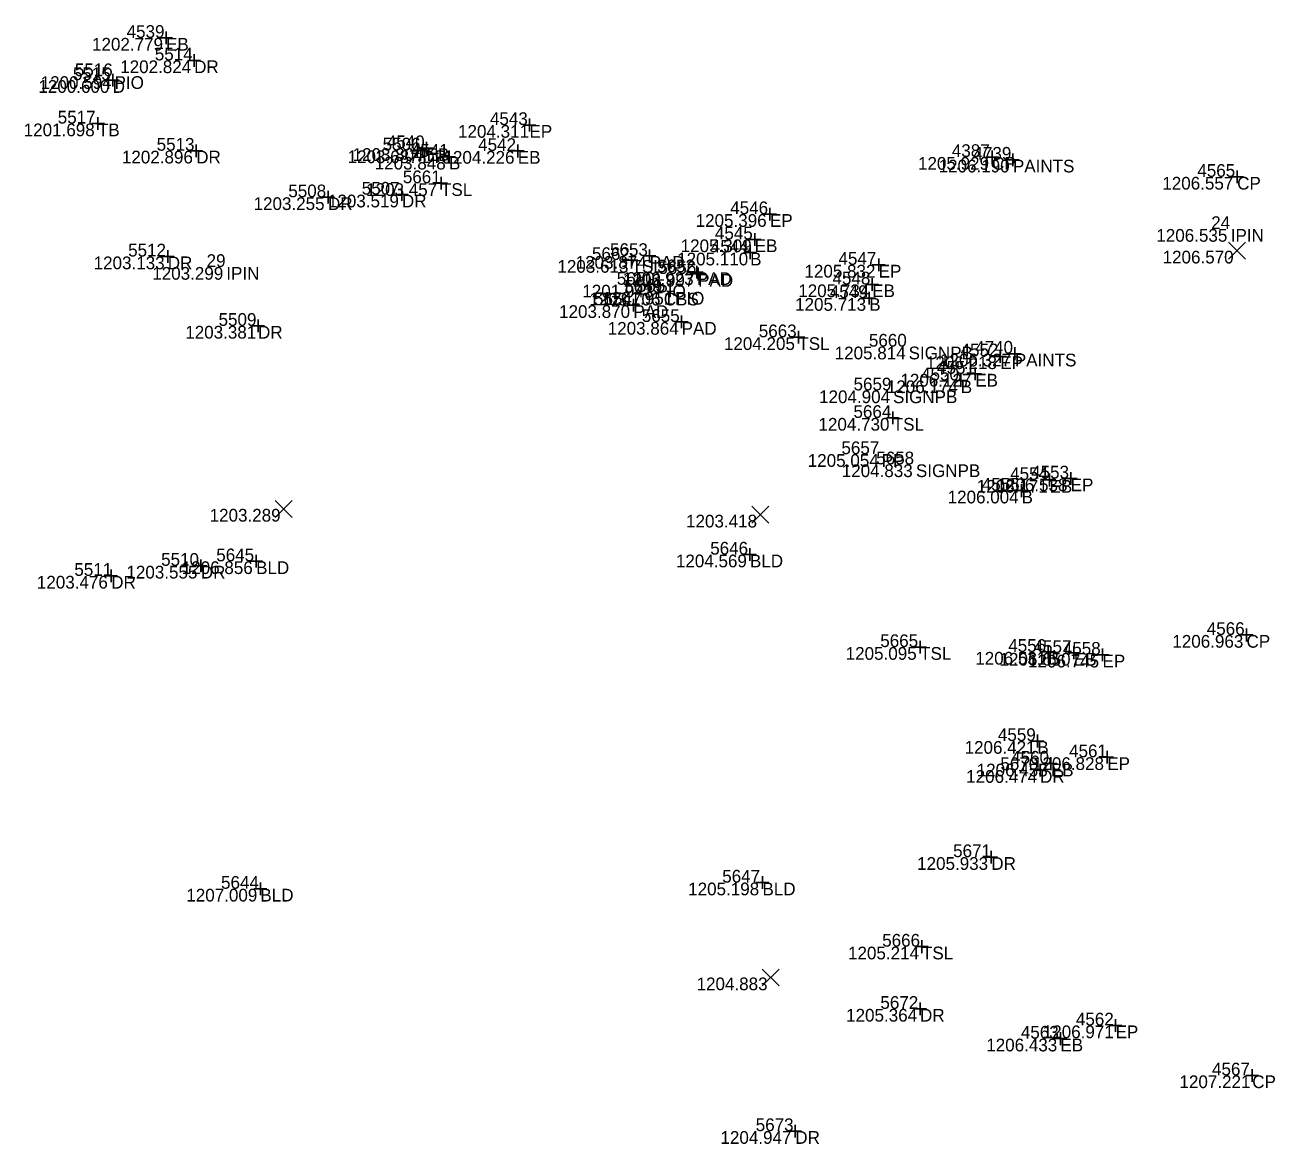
# Model space of a CAD drawing. Extents: x 2044997 to 2050342, y 455233 to 458054.
# Drawn here: x 2047537.7 to 2047635.9, y 456921.8 to 457009.8 of the extents above; entities that cross this region are included whole.
import ezdxf

# ---------------------------------------------------------------- set-up
doc = ezdxf.new("R2010")
doc.units = 0
for name, color, linetype in [('SV_X_Random_Point', 7, 'Continuous'), ('SV_X_Shot_Marker', 7, 'Continuous'), ('SV_X_Text_Comment', 7, 'Continuous'), ('SV_X_Text_Elevation', 7, 'Continuous'), ('SV_X_Text_Name', 7, 'Continuous')]:
    doc.layers.add(name, color=color, linetype=linetype)

msp = doc.modelspace()

# ---------------------------------------------------------------- linework, layer by layer
at = {"layer": 'SV_X_Random_Point'}
for p, q in [((2047632.207, 456991.355), (2047633.54, 456992.69)), ((2047632.207, 456992.69), (2047633.54, 456991.355)), ((2047557.318, 456971.065), (2047558.651, 456972.4)), ((2047557.318, 456972.4), (2047558.651, 456971.065)), ((2047594.766, 456970.602), (2047596.099, 456971.937)), ((2047594.766, 456971.937), (2047596.099, 456970.602)), ((2047595.582, 456934.228), (2047596.915, 456935.563)), ((2047595.582, 456935.563), (2047596.915, 456934.228))]:
    msp.add_line(p, q, dxfattribs=at)
at = {"layer": 'SV_X_Shot_Marker'}
for p, q in [((2047548.245, 457008.755), (2047549.245, 457008.755)), ((2047548.745, 457009.255), (2047548.745, 457008.255)), ((2047548.745, 457008.755), (2047548.745, 457008.755)), ((2047550.948, 457007.486), (2047550.948, 457006.486)), ((2047550.448, 457006.986), (2047551.448, 457006.986)), ((2047550.948, 457006.986), (2047550.948, 457006.986)), ((2047544.553, 457005.935), (2047544.553, 457004.935)), ((2047544.053, 457005.435), (2047545.053, 457005.435)), ((2047544.553, 457005.435), (2047544.553, 457005.435)), ((2047543.396, 457002.523), (2047543.396, 457001.523)), ((2047542.896, 457002.023), (2047543.896, 457002.023)), ((2047543.396, 457002.023), (2047543.396, 457002.023)), ((2047576.796, 457001.906), (2047577.796, 457001.906)), ((2047577.296, 457002.406), (2047577.296, 457001.406)), ((2047577.296, 457001.906), (2047577.296, 457001.906)), ((2047569.207, 457000.585), (2047569.207, 456999.585)), ((2047550.613, 456999.887), (2047551.613, 456999.887)), ((2047551.113, 457000.387), (2047551.113, 456999.387)), ((2047551.113, 456999.887), (2047551.113, 456999.887)), ((2047568.381, 456999.909), (2047569.381, 456999.909)), ((2047568.707, 457000.085), (2047569.707, 457000.085)), ((2047568.881, 457000.409), (2047568.881, 456999.409)), ((2047568.881, 456999.909), (2047568.881, 456999.909)), ((2047569.207, 457000.085), (2047569.207, 457000.085)), ((2047570.973, 456999.91), (2047570.973, 456998.91)), ((2047575.879, 456999.866), (2047576.879, 456999.866)), ((2047576.379, 457000.366), (2047576.379, 456999.366)), ((2047576.379, 456999.866), (2047576.379, 456999.866)), ((2047613.638, 456999.892), (2047613.638, 456998.892)), ((2047615.277, 456999.68), (2047615.277, 456998.68)), ((2047570.473, 456999.41), (2047571.473, 456999.41)), ((2047570.973, 456999.41), (2047570.973, 456999.41)), ((2047613.138, 456999.392), (2047614.138, 456999.392)), ((2047613.638, 456999.392), (2047613.638, 456999.392)), ((2047614.777, 456999.18), (2047615.777, 456999.18)), ((2047615.277, 456999.18), (2047615.277, 456999.18)), ((2047570.346, 456997.83), (2047570.346, 456996.83)), ((2047632.393, 456997.831), (2047633.393, 456997.831)), ((2047632.893, 456998.331), (2047632.893, 456997.331)), ((2047632.893, 456997.831), (2047632.893, 456997.831)), ((2047561.467, 456996.725), (2047561.467, 456995.725)), ((2047567.277, 456996.934), (2047567.277, 456995.934)), ((2047569.846, 456997.33), (2047570.846, 456997.33)), ((2047570.346, 456997.33), (2047570.346, 456997.33)), ((2047560.967, 456996.225), (2047561.967, 456996.225)), ((2047561.467, 456996.225), (2047561.467, 456996.225)), ((2047566.777, 456996.434), (2047567.777, 456996.434)), ((2047567.277, 456996.434), (2047567.277, 456996.434)), ((2047595.69, 456994.902), (2047596.69, 456994.902)), ((2047596.19, 456995.402), (2047596.19, 456994.402)), ((2047596.19, 456994.902), (2047596.19, 456994.902)), ((2047594.493, 456992.914), (2047595.493, 456992.914)), ((2047594.993, 456993.414), (2047594.993, 456992.414)), ((2047594.993, 456992.914), (2047594.993, 456992.914)), ((2047548.879, 456992.071), (2047548.879, 456991.071)), ((2047585.318, 456991.795), (2047585.318, 456990.795)), ((2047586.73, 456992.112), (2047586.73, 456991.112)), ((2047594.132, 456991.873), (2047595.132, 456991.873)), ((2047594.632, 456992.373), (2047594.632, 456991.373)), ((2047594.632, 456991.873), (2047594.632, 456991.873)), ((2047548.379, 456991.571), (2047549.379, 456991.571)), ((2047548.879, 456991.571), (2047548.879, 456991.571)), ((2047584.818, 456991.295), (2047585.818, 456991.295)), ((2047585.318, 456991.295), (2047585.318, 456991.295)), ((2047586.23, 456991.612), (2047587.23, 456991.612)), ((2047586.73, 456991.612), (2047586.73, 456991.612)), ((2047590.439, 456990.83), (2047590.439, 456989.83)), ((2047604.231, 456990.916), (2047605.231, 456990.916)), ((2047604.731, 456991.416), (2047604.731, 456990.416)), ((2047604.731, 456990.916), (2047604.731, 456990.916)), ((2047589.939, 456990.33), (2047590.939, 456990.33)), ((2047590.049, 456990.197), (2047591.049, 456990.197)), ((2047590.439, 456990.33), (2047590.439, 456990.33)), ((2047590.549, 456990.697), (2047590.549, 456989.697)), ((2047590.549, 456990.197), (2047590.549, 456990.197)), ((2047604.22, 456989.875), (2047604.22, 456988.875)), ((2047603.72, 456989.375), (2047604.72, 456989.375)), ((2047603.99, 456988.804), (2047603.99, 456987.804)), ((2047604.22, 456989.375), (2047604.22, 456989.375)), ((2047585.459, 456988.242), (2047585.459, 456987.242)), ((2047603.49, 456988.304), (2047604.49, 456988.304)), ((2047603.99, 456988.304), (2047603.99, 456988.304)), ((2047584.959, 456987.742), (2047585.959, 456987.742)), ((2047585.459, 456987.742), (2047585.459, 456987.742)), ((2047589.25, 456986.925), (2047589.25, 456985.925)), ((2047555.469, 456986.118), (2047556.469, 456986.118)), ((2047555.969, 456986.618), (2047555.969, 456985.618)), ((2047555.969, 456986.118), (2047555.969, 456986.118)), ((2047588.75, 456986.425), (2047589.75, 456986.425)), ((2047589.25, 456986.425), (2047589.25, 456986.425)), ((2047597.919, 456985.221), (2047598.919, 456985.221)), ((2047598.419, 456985.721), (2047598.419, 456984.721)), ((2047598.419, 456985.221), (2047598.419, 456985.221)), ((2047614.279, 456984.222), (2047614.279, 456983.222)), ((2047614.931, 456983.932), (2047615.931, 456983.932)), ((2047615.431, 456984.432), (2047615.431, 456983.432)), ((2047615.431, 456983.932), (2047615.431, 456983.932)), ((2047613.779, 456983.722), (2047614.779, 456983.722)), ((2047614.279, 456983.722), (2047614.279, 456983.722)), ((2047611.179, 456982.33), (2047611.179, 456981.33)), ((2047611.816, 456982.348), (2047612.816, 456982.348)), ((2047612.316, 456982.848), (2047612.316, 456981.848)), ((2047612.316, 456982.348), (2047612.316, 456982.348)), ((2047610.679, 456981.83), (2047611.679, 456981.83)), ((2047611.179, 456981.83), (2047611.179, 456981.83)), ((2047605.838, 456979.381), (2047605.838, 456978.381)), ((2047605.338, 456978.881), (2047606.338, 456978.881)), ((2047605.838, 456978.881), (2047605.838, 456978.881)), ((2047618.151, 456974.504), (2047618.151, 456973.504)), ((2047619.317, 456974.119), (2047620.317, 456974.119)), ((2047619.817, 456974.619), (2047619.817, 456973.619)), ((2047619.817, 456974.119), (2047619.817, 456974.119)), ((2047615.456, 456973.164), (2047616.456, 456973.164)), ((2047615.956, 456973.664), (2047615.956, 456972.664)), ((2047615.956, 456973.164), (2047615.956, 456973.164)), ((2047617.651, 456974.004), (2047618.651, 456974.004)), ((2047618.151, 456974.004), (2047618.151, 456974.004)), ((2047594.617, 456968.638), (2047594.617, 456967.638)), ((2047550.977, 456967.258), (2047551.977, 456967.258)), ((2047551.477, 456967.758), (2047551.477, 456966.758)), ((2047551.477, 456967.258), (2047551.477, 456967.258)), ((2047555.318, 456967.611), (2047556.318, 456967.611)), ((2047555.818, 456968.111), (2047555.818, 456967.111)), ((2047555.818, 456967.611), (2047555.818, 456967.611)), ((2047594.117, 456968.138), (2047595.117, 456968.138)), ((2047594.617, 456968.138), (2047594.617, 456968.138)), ((2047543.934, 456966.468), (2047544.934, 456966.468)), ((2047544.434, 456966.968), (2047544.434, 456965.968)), ((2047544.434, 456966.468), (2047544.434, 456966.468)), ((2047633.629, 456962.32), (2047633.629, 456961.32)), ((2047607.986, 456961.369), (2047607.986, 456960.369)), ((2047633.129, 456961.82), (2047634.129, 456961.82)), ((2047633.629, 456961.82), (2047633.629, 456961.82)), ((2047607.486, 456960.869), (2047608.486, 456960.869)), ((2047607.986, 456960.869), (2047607.986, 456960.869)), ((2047617.535, 456960.491), (2047618.535, 456960.491)), ((2047618.035, 456960.991), (2047618.035, 456959.991)), ((2047618.035, 456960.491), (2047618.035, 456960.491)), ((2047619.563, 456960.41), (2047620.563, 456960.41)), ((2047620.063, 456960.91), (2047620.063, 456959.91)), ((2047620.063, 456960.41), (2047620.063, 456960.41)), ((2047622.315, 456960.767), (2047622.315, 456959.767)), ((2047621.815, 456960.267), (2047622.815, 456960.267)), ((2047622.315, 456960.267), (2047622.315, 456960.267)), ((2047616.697, 456953.484), (2047617.697, 456953.484)), ((2047617.197, 456953.984), (2047617.197, 456952.984)), ((2047617.197, 456953.484), (2047617.197, 456953.484)), ((2047622.687, 456952.707), (2047622.687, 456951.707)), ((2047617.412, 456951.698), (2047617.412, 456950.698)), ((2047617.756, 456951.705), (2047618.756, 456951.705)), ((2047618.256, 456952.205), (2047618.256, 456951.205)), ((2047618.256, 456951.705), (2047618.256, 456951.705)), ((2047622.187, 456952.207), (2047623.187, 456952.207)), ((2047622.687, 456952.207), (2047622.687, 456952.207)), ((2047616.912, 456951.198), (2047617.912, 456951.198)), ((2047617.412, 456951.198), (2047617.412, 456951.198)), ((2047613.577, 456944.856), (2047613.577, 456943.856)), ((2047613.077, 456944.356), (2047614.077, 456944.356)), ((2047613.577, 456944.356), (2047613.577, 456944.356)), ((2047595.599, 456942.854), (2047595.599, 456941.854)), ((2047555.654, 456941.869), (2047556.654, 456941.869)), ((2047556.154, 456942.369), (2047556.154, 456941.369)), ((2047556.154, 456941.869), (2047556.154, 456941.869)), ((2047595.099, 456942.354), (2047596.099, 456942.354)), ((2047595.599, 456942.354), (2047595.599, 456942.354)), ((2047608.129, 456937.82), (2047608.129, 456936.82)), ((2047607.629, 456937.32), (2047608.629, 456937.32)), ((2047608.129, 456937.32), (2047608.129, 456937.32)), ((2047607.979, 456932.93), (2047607.979, 456931.93)), ((2047607.479, 456932.43), (2047608.479, 456932.43)), ((2047607.979, 456932.43), (2047607.979, 456932.43)), ((2047622.84, 456931.125), (2047623.84, 456931.125)), ((2047623.34, 456931.625), (2047623.34, 456930.625)), ((2047623.34, 456931.125), (2047623.34, 456931.125)), ((2047618.508, 456930.088), (2047619.508, 456930.088)), ((2047619.008, 456930.588), (2047619.008, 456929.588)), ((2047619.008, 456930.088), (2047619.008, 456930.088)), ((2047633.58, 456927.2), (2047634.58, 456927.2)), ((2047634.08, 456927.7), (2047634.08, 456926.7)), ((2047634.08, 456927.2), (2047634.08, 456927.2)), ((2047598.179, 456923.32), (2047598.179, 456922.32)), ((2047597.679, 456922.82), (2047598.679, 456922.82)), ((2047598.179, 456922.82), (2047598.179, 456922.82))]:
    msp.add_line(p, q, dxfattribs=at)

# ---------------------------------------------------------------- texts
at = {"layer": 'SV_X_Text_Comment'}
for s, p in [('EB', (2047548.745, 457007.755)), ('DR', (2047550.948, 457005.986)), ('PIO', (2047544.698, 457004.743)), ('D', (2047544.553, 457004.435)), ('TB', (2047543.396, 457001.023)), ('EP', (2047577.296, 457000.906)), ('DR', (2047551.113, 456998.887)), ('DR', (2047568.881, 456998.909)), ('EB', (2047569.207, 456999.085)), ('EB', (2047576.379, 456998.866)), ('B', (2047570.973, 456998.41)), ('CP', (2047613.638, 456998.392)), ('PAINTS', (2047615.277, 456998.18)), ('CP', (2047632.893, 456996.831)), ('TSL', (2047570.346, 456996.33)), ('DR', (2047561.467, 456995.225)), ('DR', (2047567.277, 456995.434)), ('EP', (2047596.19, 456993.902)), ('IPIN', (2047632.392, 456992.732)), ('EB', (2047594.993, 456991.914)), ('B', (2047594.632, 456990.873)), ('DR', (2047548.879, 456990.571)), ('IPIN', (2047553.477, 456989.746)), ('TSL', (2047585.318, 456990.295)), ('PAD', (2047586.73, 456990.612)), ('EP', (2047604.731, 456989.916)), ('PAD', (2047590.439, 456989.33)), ('PAD', (2047590.549, 456989.197)), ('PIO', (2047587.273, 456988.349)), ('PIO', (2047588.731, 456987.787)), ('EB', (2047604.22, 456988.375)), ('CBS', (2047587.843, 456987.726)), ('B', (2047603.99, 456987.304)), ('PAD', (2047585.459, 456986.742)), ('DR', (2047555.969, 456985.118)), ('PAD', (2047589.25, 456985.425)), ('TSL', (2047598.419, 456984.221)), ('SIGNPB', (2047607.081, 456983.486)), ('PAINTS', (2047615.431, 456982.932)), ('EP', (2047614.279, 456982.722)), ('EB', (2047612.316, 456981.348)), ('SIGNPB', (2047605.856, 456980.044)), ('B', (2047611.179, 456980.83)), ('TSL', (2047605.838, 456977.881)), ('PP', (2047604.965, 456975.036)), ('SIGNPB', (2047607.656, 456974.232)), ('EP', (2047619.817, 456973.119)), ('B', (2047615.956, 456972.164)), ('EB', (2047618.151, 456973.004)), ('DR', (2047551.477, 456966.258)), ('BLD', (2047555.818, 456966.611)), ('BLD', (2047594.617, 456967.138)), ('DR', (2047544.434, 456965.468)), ('CP', (2047633.629, 456960.82)), ('TSL', (2047607.986, 456959.869)), ('B', (2047618.035, 456959.491)), ('EB', (2047620.063, 456959.41)), ('EP', (2047622.315, 456959.267)), ('B', (2047617.197, 456952.484)), ('EB', (2047618.256, 456950.705)), ('EP', (2047622.687, 456951.207)), ('DR', (2047617.412, 456950.198)), ('DR', (2047613.577, 456943.356)), ('BLD', (2047556.154, 456940.869)), ('BLD', (2047595.599, 456941.354)), ('TSL', (2047608.129, 456936.32)), ('DR', (2047607.979, 456931.43)), ('EP', (2047623.34, 456930.125)), ('EB', (2047619.008, 456929.088)), ('CP', (2047634.08, 456926.2)), ('DR', (2047598.179, 456921.82))]:
    msp.add_text(s, height=1, dxfattribs=at).set_placement(p)
at = {"layer": 'SV_X_Text_Elevation'}
for s, p in [('1202.779', (2047542.927, 457007.755)), ('1202.824', (2047545.141, 457005.986)), ('1200.594', (2047538.89, 457004.743)), ('1200.600', (2047538.715, 457004.435)), ('1201.698', (2047537.56, 457001.023)), ('1204.311', (2047571.683, 457000.906)), ('1202.896', (2047545.273, 456998.887)), ('1203.687', (2047563.002, 456998.909)), ('1203.804', (2047563.4, 456999.085)), ('1204.226', (2047570.539, 456998.866)), ('1203.848', (2047565.137, 456998.41)), ('1205.929', (2047607.821, 456998.392)), ('1206.190', (2047609.439, 456998.18)), ('1206.557', (2047627.014, 456996.831)), ('1203.457', (2047564.466, 456996.33)), ('1203.255', (2047555.619, 456995.225)), ('1203.519', (2047561.459, 456995.434)), ('1205.396', (2047590.35, 456993.902)), ('1206.535', (2047626.545, 456992.732)), ('1205.309', (2047589.175, 456991.914)), ('1205.110', (2047588.898, 456990.873)), ('1206.570', (2047627.036, 456991.023)), ('1203.133', (2047543.053, 456990.571)), ('1203.299', (2047547.659, 456989.746)), ('1203.613', (2047579.492, 456990.295)), ('1203.874', (2047580.922, 456990.612)), ('1205.832', (2047598.898, 456989.916)), ('1203.923', (2047584.613, 456989.33)), ('1203.997', (2047584.669, 456989.197)), ('1201.943', (2047581.447, 456988.349)), ('1201.951', (2047583.013, 456987.787)), ('1205.734', (2047598.412, 456988.375)), ('1203.706', (2047582.002, 456987.726)), ('1205.713', (2047598.164, 456987.304)), ('1203.870', (2047579.622, 456986.742)), ('1203.381', (2047550.252, 456985.118)), ('1203.864', (2047583.442, 456985.425)), ('1204.205', (2047592.571, 456984.221)), ('1205.814', (2047601.273, 456983.486)), ('1206.327', (2047609.551, 456982.932)), ('1206.218', (2047608.443, 456982.722)), ('1206.127', (2047606.437, 456981.348)), ('1204.904', (2047600.048, 456980.044)), ('1206.174', (2047605.371, 456980.83)), ('1204.730', (2047600, 456977.881)), ('1205.054', (2047599.157, 456975.036)), ('1204.833', (2047601.829, 456974.232)), ('1206.538', (2047613.981, 456973.119)), ('1206.004', (2047610.148, 456972.164)), ('1206.171', (2047612.434, 456973.004)), ('1203.289', (2047552.166, 456970.733)), ('1203.418', (2047589.596, 456970.269)), ('1204.569', (2047588.799, 456967.138)), ('1203.555', (2047545.629, 456966.258)), ('1206.856', (2047549.977, 456966.611)), ('1203.476', (2047538.593, 456965.468)), ('1206.963', (2047627.802, 456960.82)), ('1205.095', (2047602.138, 456959.869)), ('1206.531', (2047612.318, 456959.491)), ('1206.650', (2047614.225, 456959.41)), ('1206.745', (2047616.468, 456959.267)), ('1206.421', (2047611.48, 456952.484)), ('1206.453', (2047612.43, 456950.705)), ('1206.828', (2047616.851, 456951.207)), ('1206.474', (2047611.604, 456950.198)), ('1205.933', (2047607.751, 456943.356)), ('1207.009', (2047550.336, 456940.869)), ('1205.198', (2047589.763, 456941.354)), ('1205.214', (2047602.321, 456936.32)), ('1204.883', (2047590.422, 456933.895)), ('1205.364', (2047602.171, 456931.43)), ('1206.971', (2047617.623, 456930.125)), ('1206.433', (2047613.182, 456929.088)), ('1207.221', (2047628.362, 456926.2)), ('1204.947', (2047592.299, 456921.82))]:
    msp.add_text(s, height=1, dxfattribs=at).set_placement(p)
at = {"layer": 'SV_X_Text_Name'}
for s, p in [('4539', (2047545.645, 457008.755)), ('5514', (2047547.859, 457006.986)), ('5516', (2047541.575, 457005.743)), ('5515', (2047541.423, 457005.435)), ('5517', (2047540.234, 457002.023)), ('4543', (2047574.188, 457001.906)), ('5513', (2047548.005, 456999.887)), ('5506', (2047565.759, 456999.909)), ('4540', (2047566.088, 457000.085)), ('4542', (2047573.264, 456999.866)), ('4541', (2047567.973, 456999.41)), ('4387', (2047610.477, 456999.392)), ('4739', (2047612.177, 456999.18)), ('4565', (2047629.764, 456997.831)), ('5661', (2047567.346, 456997.33)), ('5508', (2047558.348, 456996.225)), ('5507', (2047564.116, 456996.434)), ('4546', (2047593.068, 456994.902)), ('24', (2047630.856, 456993.732)), ('4545', (2047591.864, 456992.914)), ('4544', (2047591.542, 456991.873)), ('5512', (2047545.764, 456991.571)), ('29', (2047551.93, 456990.746)), ('5662', (2047582.203, 456991.295)), ('5653', (2047583.622, 456991.612)), ('4547', (2047601.57, 456990.916)), ('5652', (2047587.324, 456990.33)), ('5656', (2047587.426, 456990.197)), ('5650', (2047584.154, 456989.349)), ('5651', (2047585.731, 456988.787)), ('4548', (2047601.102, 456989.375)), ('5649', (2047584.743, 456988.726)), ('4549', (2047600.89, 456988.304)), ('5654', (2047582.369, 456987.742)), ('5509', (2047552.869, 456986.118)), ('5655', (2047586.12, 456986.425)), ('5663', (2047595.31, 456985.221)), ('5660', (2047603.961, 456984.486)), ('4740', (2047612.311, 456983.932)), ('4552', (2047611.164, 456983.722)), ('4551', (2047609.317, 456982.348)), ('5659', (2047602.756, 456981.044)), ('4550', (2047608.059, 456981.83)), ('5664', (2047602.748, 456978.881)), ('5657', (2047601.804, 456976.036)), ('5658', (2047604.538, 456975.232)), ('4553', (2047616.709, 456974.119)), ('4555', (2047612.826, 456973.164)), ('4554', (2047615.061, 456974.004)), ('5646', (2047591.495, 456968.138)), ('5510', (2047548.357, 456967.258)), ('5645', (2047552.688, 456967.611)), ('5511', (2047541.538, 456966.468)), ('4566', (2047630.506, 456961.82)), ('5665', (2047604.856, 456960.869)), ('4556', (2047614.912, 456960.491)), ('4557', (2047616.901, 456960.41)), ('4558', (2047619.197, 456960.267)), ('4559', (2047614.097, 456953.484)), ('4560', (2047615.136, 456951.705)), ('4561', (2047619.688, 456952.207)), ('5670', (2047614.292, 456951.198)), ('5671', (2047610.578, 456944.356)), ('5644', (2047553.064, 456941.869)), ('5647', (2047592.438, 456942.354)), ('5666', (2047605.006, 456937.32)), ('5672', (2047604.864, 456932.43)), ('4562', (2047620.225, 456931.125)), ('4563', (2047615.9, 456930.088)), ('4567', (2047630.918, 456927.2)), ('5673', (2047595.07, 456922.82))]:
    msp.add_text(s, height=1, dxfattribs=at).set_placement(p)

doc.saveas('drawing.dxf')
